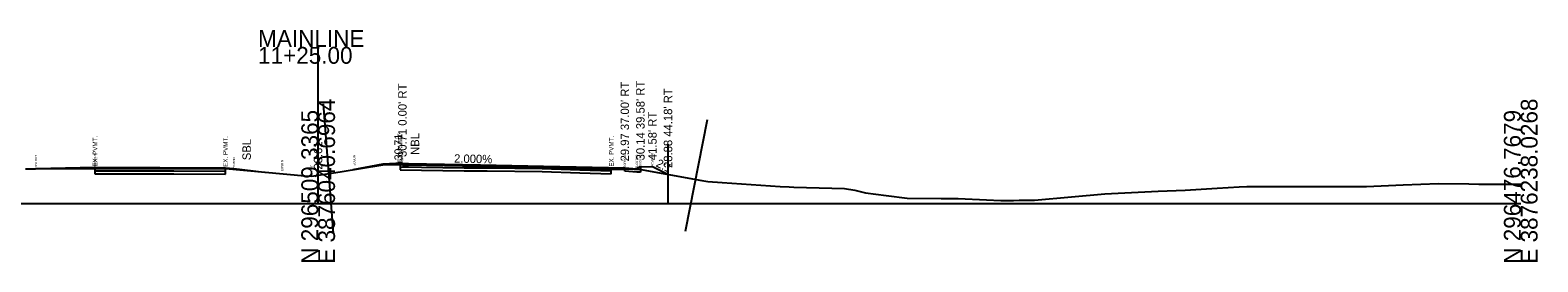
# Model space of a CAD drawing. Extents: x 14823 to 15251, y 114839 to 117377.
# Drawn here: x 15000.5 to 15251.2, y 117338.7 to 117377.2 of the extents above; entities that cross this region are included whole.
import ezdxf

# ---------------------------------------------------------------- set-up
doc = ezdxf.new("R2010")
doc.units = 0
for name, color, linetype in [('Default', 7, 'Continuous'), ('Level 1', 7, 'Continuous'), ('Level 10', 7, 'Continuous'), ('Level 11', 7, 'Continuous'), ('Level 2', 7, 'Continuous'), ('Level 25', 7, 'Continuous'), ('Level 3', 7, 'Continuous'), ('Level 4', 7, 'Continuous'), ('Level 42', 7, 'Continuous'), ('Level 49', 7, 'Continuous'), ('Level 50', 7, 'Continuous'), ('Level 51', 7, 'Continuous'), ('Level 52', 7, 'Continuous'), ('Level 53', 7, 'Continuous'), ('Level 56', 7, 'Continuous'), ('Level 59', 7, 'Continuous'), ('Level 63', 7, 'Continuous')]:
    doc.layers.add(name, color=color, linetype=linetype)

msp = doc.modelspace()

# ---------------------------------------------------------------- linework, layer by layer
at = {"layer": 'Default'}
for p, q in [((15049.2, 117364.99), (15050.86, 117343.38)), ((15113.04, 117362.33), (15109.38, 117343.71))]:
    msp.add_line(p, q, dxfattribs=at)
at = {"layer": 'Level 1'}
for p, q in [((14999.66, 117354.14), (15001.36, 117354.14)), ((15001.36, 117354.14), (15011.24, 117354.23)), ((15011.24, 117354.23), (15019.42, 117354.23)), ((15019.42, 117354.23), (15022, 117354.24)), ((15022, 117354.24), (15024.36, 117354.22)), ((15024.36, 117354.22), (15032.94, 117354.2)), ((15032.94, 117354.2), (15046.12, 117353.02)), ((15048.36, 117353.09), (15052.03, 117353.66)), ((15052.03, 117353.66), (15059.1, 117354.82)), ((15059.1, 117354.82), (15060.74, 117354.86)), ((15060.74, 117354.86), (15061.97, 117354.89)), ((15061.97, 117354.89), (15072.65, 117354.74)), ((15072.65, 117354.74), (15074.24, 117354.72)), ((15074.24, 117354.72), (15076.44, 117354.71)), ((15076.44, 117354.71), (15085.64, 117354.6)), ((15085.64, 117354.6), (15091.89, 117354.4)), ((15091.89, 117354.4), (15097.11, 117354.23)), ((15097.11, 117354.23), (15100.86, 117354.11)), ((15100.86, 117354.11), (15101.76, 117354.11)), ((15101.76, 117354.11), (15112.17, 117352.23)), ((15046.12, 117353.02), (15047.23, 117352.92)), ((15047.23, 117352.92), (15048.36, 117353.09)), ((15112.17, 117352.23), (15113.16, 117352.05)), ((15113.16, 117352.05), (15115.53, 117351.89)), ((15115.53, 117351.89), (15125.17, 117351.21)), ((15125.17, 117351.21), (15126.67, 117351.16)), ((15126.67, 117351.16), (15127.48, 117351.09)), ((15127.48, 117351.09), (15135.91, 117350.89)), ((15135.91, 117350.89), (15137.61, 117350.59)), ((15192.54, 117350.62), (15197.9, 117350.96)), ((15197.9, 117350.96), (15201.55, 117351.18)), ((15201.55, 117351.18), (15202.83, 117351.19)), ((15202.83, 117351.19), (15214.61, 117351.21)), ((15214.61, 117351.21), (15217.06, 117351.21)), ((15217.06, 117351.21), (15222.73, 117351.21)), ((15222.73, 117351.21), (15228.83, 117351.51)), ((15228.83, 117351.51), (15234.67, 117351.71)), ((15234.67, 117351.71), (15239.7, 117351.64)), ((15239.7, 117351.64), (15241.39, 117351.62)), ((15241.39, 117351.62), (15243, 117351.62)), ((15243, 117351.62), (15248.36, 117351.6)), ((15137.61, 117350.59), (15139.4, 117350.19)), ((15139.4, 117350.19), (15142.81, 117349.73)), ((15142.81, 117349.73), (15146.3, 117349.28)), ((15146.3, 117349.28), (15151.97, 117349.24)), ((15151.97, 117349.24), (15154.78, 117349.24)), ((15154.78, 117349.24), (15159.53, 117348.99)), ((15159.53, 117348.99), (15161.91, 117348.87)), ((15161.91, 117348.87), (15162.24, 117348.88)), ((15162.24, 117348.88), (15164, 117348.91)), ((15164, 117348.91), (15164.92, 117348.93)), ((15164.92, 117348.93), (15167.48, 117348.92)), ((15167.48, 117348.92), (15173.63, 117349.48)), ((15173.63, 117349.48), (15179.19, 117350.01)), ((15179.19, 117350.01), (15188.04, 117350.42)), ((15188.04, 117350.42), (15192.54, 117350.62))]:
    msp.add_line(p, q, dxfattribs=at)
at = {"layer": 'Level 10'}
for p, q in [((15034.36, 117354.2), (15034.36, 117354.07)), ((15059.1, 117354.81), (15059.1, 117354.94)), ((15062.37, 117354.95), (15062.37, 117355.08)), ((15062.37, 117354.79), (15062.37, 117354.95)), ((15062.37, 117354.95), (15063.36, 117354.93)), ((15062.37, 117354.79), (15063.36, 117354.77)), ((15075.37, 117354.69), (15063.36, 117354.93)), ((15075.37, 117354.53), (15063.36, 117354.77)), ((15085.86, 117354.48), (15075.37, 117354.69)), ((15085.86, 117354.32), (15075.37, 117354.53)), ((15085.86, 117354.48), (15099.36, 117354.21)), ((15085.86, 117354.32), (15099.36, 117354.05)), ((15099.36, 117354.21), (15099.36, 117354.34)), ((15099.36, 117354.05), (15099.36, 117354.21))]:
    msp.add_line(p, q, dxfattribs=at)
at = {"layer": 'Level 11'}
for p, q in [((15099.36, 117353.75), (15099.36, 117354.34)), ((15101.36, 117353.59), (15099.36, 117353.75)), ((15101.95, 117353.59), (15101.36, 117353.59)), ((15101.95, 117354.5), (15101.95, 117353.59))]:
    msp.add_line(p, q, dxfattribs=at)
at = {"layer": 'Level 2'}
for p, q in [((15011.24, 117354.36), (15001.44, 117354.14)), ((15011.24, 117354.36), (15019.42, 117354.36)), ((15019.42, 117354.36), (15022, 117354.37)), ((15022, 117354.37), (15024.36, 117354.35)), ((15024.36, 117354.35), (15032.94, 117354.33)), ((15032.95, 117354.33), (15034.36, 117354.2)), ((15062.37, 117355.08), (15059.1, 117354.94)), ((15062.37, 117355.08), (15063.36, 117355.06)), ((15063.36, 117355.06), (15075.37, 117354.82)), ((15075.37, 117354.82), (15085.86, 117354.61)), ((15085.86, 117354.61), (15099.36, 117354.34))]:
    msp.add_line(p, q, dxfattribs=at)
at = {"layer": 'Level 25'}
msp.add_line((15106.54, 117358.25), (15106.54, 117348.25), dxfattribs=at)
at = {"layer": 'Level 3'}
for p, q in [((15034.36, 117354.2), (15039.36, 117353.63)), ((15059.1, 117354.94), (15054.1, 117354)), ((15099.36, 117354.34), (15101.36, 117354.17)), ((15101.36, 117354.25), (15101.78, 117354.5)), ((15101.36, 117354.17), (15101.36, 117354.25)), ((15101.78, 117354.5), (15101.95, 117354.5))]:
    msp.add_line(p, q, dxfattribs=at)
at = {"layer": 'Level 4'}
for p, q in [((15101.95, 117354.5), (15103.95, 117354.54)), ((15103.95, 117354.54), (15106.54, 117353.25))]:
    msp.add_line(p, q, dxfattribs=at)
at = {"layer": 'Level 59'}
for p, q in [((15011.24, 117354.23), (15011.24, 117353.81)), ((15011.24, 117353.81), (15019.42, 117353.82)), ((15011.24, 117353.81), (15011.24, 117353.31)), ((15019.42, 117353.82), (15022, 117353.82)), ((15022, 117353.82), (15024.36, 117353.81)), ((15024.36, 117353.81), (15032.94, 117353.79)), ((15032.94, 117353.79), (15032.94, 117354.2)), ((15032.94, 117353.79), (15032.94, 117353.79)), ((15032.94, 117353.29), (15032.94, 117353.79)), ((15061.97, 117354.89), (15061.97, 117354.48)), ((15061.97, 117354.48), (15072.65, 117354.33)), ((15061.97, 117354.48), (15061.97, 117354.48)), ((15061.97, 117354.48), (15061.97, 117353.98)), ((15061.97, 117353.98), (15072.65, 117353.83)), ((15061.97, 117353.98), (15061.97, 117353.98)), ((15072.65, 117354.33), (15074.24, 117354.3)), ((15072.65, 117353.83), (15074.24, 117353.8)), ((15074.24, 117354.3), (15076.44, 117354.3)), ((15074.24, 117353.8), (15076.44, 117353.8)), ((15076.44, 117354.3), (15085.64, 117354.19)), ((15076.44, 117353.8), (15085.64, 117353.69)), ((15085.64, 117354.19), (15091.89, 117353.98)), ((15085.64, 117353.69), (15091.89, 117353.48)), ((15091.89, 117353.98), (15097.11, 117353.81)), ((15091.89, 117353.48), (15097.11, 117353.31)), ((15097.11, 117353.81), (15097.11, 117354.23)), ((15097.11, 117353.31), (15097.11, 117353.81)), ((15011.24, 117353.31), (15019.42, 117353.32)), ((15019.42, 117353.32), (15022, 117353.32)), ((15022, 117353.32), (15024.36, 117353.31)), ((15024.36, 117353.31), (15032.94, 117353.29)), ((15032.94, 117353.29), (15032.94, 117353.29))]:
    msp.add_line(p, q, dxfattribs=at)
at = {"layer": 'Level 63'}
for p, q in [((15048.36, 117348.36), (15048.36, 117374.45)), ((14848.36, 117348.36), (15048.36, 117348.36)), ((15048.36, 117348.36), (15248.36, 117348.36))]:
    msp.add_line(p, q, dxfattribs=at)

# ---------------------------------------------------------------- texts
at = {"layer": 'Level 42'}
for s, p in [('SBL', (15037.16, 117355.6)), ('NBL', (15065.16, 117356.48))]:
    msp.add_text(s, height=1.4, rotation=90, dxfattribs=at).set_placement(p)
at = {"layer": 'Level 49'}
msp.add_text('2.000%', height=1.4, rotation=358.8542, dxfattribs=at).set_placement((15070.95, 117355.19))
at = {"layer": 'Level 50'}
msp.add_text('2:1', height=1.4, rotation=333.435, dxfattribs=at).set_placement((15104.42, 117354.62))
at = {"layer": 'Level 51'}
msp.add_text('28.61', height=1.4, rotation=90, dxfattribs=at).set_placement((15049.04, 117354.03))
at = {"layer": 'Level 52'}
for s, p in [("29.97 37.00' RT", (15100.06, 117355.39)), ("30.14 39.58' RT", (15102.65, 117355.56)), ("30.71 0.00' RT", (15063.07, 117356.13)), ("28.88 44.18' RT", (15107.24, 117354.3)), ("41.58' RT", (15104.65, 117355.6))]:
    msp.add_text(s, height=1.4, rotation=90, dxfattribs=at).set_placement(p)
at = {"layer": 'Level 53'}
for p in [(15011.62, 117354.23), (15033.32, 117354.2), (15062.35, 117354.89), (15097.49, 117354.23)]:
    msp.add_text(' EX. PVMT.', height=0.75, rotation=90, dxfattribs=at).set_placement(p)
at = {"layer": 'Level 56'}
for s, p in [('EOSLOUT', (15001.62, 117354.14)), ('EOPLOUT', (15011.42, 117354.36)), ('EOPRIN', (15034.54, 117354.2)), ('EOSLIN', (15054.54, 117354.68)), ('EOPLIN', (15062.54, 117355.08)), ('EOPROUT', (15099.54, 117354.34)), ('FLCURBR', (15101.54, 117354.25)), ('BKCURBR', (15102.12, 117354.5)), ('RCVRBLR', (15104.12, 117354.54)), ('EOSRIN', (15042.54, 117353.8)), ('MEDDIT', (15047.46, 117352.98)), ('FRDTCHR', (15106.72, 117353.25))]:
    msp.add_text(s, height=0.35, rotation=90, dxfattribs=at).set_placement(p)
at = {"layer": 'Level 63'}
for s, p in [('MAINLINE', (15038.37, 117374.45)), ('11+25.00', (15038.36, 117371.65))]:
    msp.add_text(s, height=2.8, dxfattribs=at).set_placement(p)
for s, height, p in [('N 296509.3365', 2.8, (15048.36, 117338.36)), ('E 3876040.6964', 2.8, (15051.16, 117338.36)), ('N 296476.7679', 2.8, (15248.36, 117338.36)), ('E 3876238.0268', 2.8, (15251.16, 117338.37)), (' 30.71', 1.32, (15062.36, 117355.08))]:
    msp.add_text(s, height=height, rotation=90, dxfattribs=at).set_placement(p)

doc.saveas('drawing.dxf')
